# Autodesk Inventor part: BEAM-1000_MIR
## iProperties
Created: 2007-08
Part Number: BEAM-1000_MIR
Material: Aluminum-6061
Document SubType Name: Modeling
Density: 2.71 g/cm^3
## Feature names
1. Derived Body1 [Tagging]
